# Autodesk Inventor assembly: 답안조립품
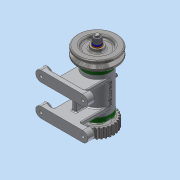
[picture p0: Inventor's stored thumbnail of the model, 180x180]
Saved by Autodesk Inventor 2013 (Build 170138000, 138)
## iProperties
Created: 2015-11
Part Number: 답안조립품
Document SubType Name: Assembly
Designer: Administrator
Author: Administrator
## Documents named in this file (16)
- C:\Users\Administrator\Desktop\451110V1044\답안조립품.iam
- C:\Users\Administrator\Desktop\451110V1044\본체.ipt
- C:\Users\Administrator\Desktop\451110V1044\V벨트풀리.ipt
- C:\Users\Administrator\Desktop\451110V1044\너트 M 8.ipt
- C:\Users\Administrator\Desktop\451110V1044\니플 M 6 x 0.75.ipt
- C:\Users\Administrator\Desktop\451110V1044\베어링 15 x 32 x 9.ipt
- C:\Users\Administrator\Desktop\451110V1044\볼트 M 6 x 8.ipt
- C:\Users\Administrator\Desktop\451110V1044\볼트 M4 x 12.ipt
- C:\Users\Administrator\Desktop\451110V1044\스퍼기어.ipt
- C:\Users\Administrator\Desktop\451110V1044\스프링와셔 8.ipt
- C:\Users\Administrator\Desktop\451110V1044\오일 실 15 25 7.ipt
- C:\Users\Administrator\Desktop\451110V1044\와셔 6x11.5.ipt
- C:\Users\Administrator\Desktop\451110V1044\와셔 8x17.ipt
- C:\Users\Administrator\Desktop\451110V1044\축.ipt
- C:\Users\Administrator\Desktop\451110V1044\커버.ipt
- C:\Users\Administrator\Desktop\451110V1044\키 3 x 3 x 12.ipt
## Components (11 placed, 3 different names)
1. KS B 2023 6002 - 15 x 32 x 9:1
2. V벨트풀리:2
3. KS B 2023 6002 - 15 x 32 x 9:2
4. ISO 4762 M4 x 12:1
5. ISO 4762 M4 x 12:3
6. ISO 4762 M4 x 12:4
7. ISO 4762 M4 x 12:5
8. ISO 4762 M4 x 12:2
9. ISO 4762 M4 x 12:6
10. ISO 4762 M4 x 12:7
11. ISO 4762 M4 x 12:8
